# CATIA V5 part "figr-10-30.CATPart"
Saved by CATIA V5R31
Part number: Part1
Bounding box of the stored display mesh (mm): x -72 to 28.909, y -84.823 to 54.826, z -29.324 to 42.024
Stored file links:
  D:\PROJECTS\Project 2021\US EDITION\CATIA V5 6R 2021\Resources\Part Files\c10_catia_v5_6r2021_prt\c10_catia_v5_6r2021_prt\figr-10-30.CATPart
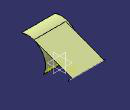
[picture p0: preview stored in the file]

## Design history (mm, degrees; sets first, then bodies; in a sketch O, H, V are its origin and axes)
Body1 (main body)
  Sketch1 on yz-plane, origin (0, 0, 0), H (0, 1, 0), V (0, 0, 1)
    arc A1 centre (-67.861, -7.2287) radius 49.2558 from (-84.8225, 39.0145) to (-23.8391, -29.3242) cw
  Extrude1: Element1 Sketch1, Lim1 20, Lim2 72
  Sketch2 on xy-plane, origin (0, 0, 0), H (1, 0, 0), V (0, 1, 0)
    line L1 (-67.3145, 54.8256) -> (28.9089, 54.8256)
    horizontal: L1 H
  Sweep1: type Segment, GuideCrv Sketch2, GuideSurf Extrude1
